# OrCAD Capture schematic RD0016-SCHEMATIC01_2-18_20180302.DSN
size A3
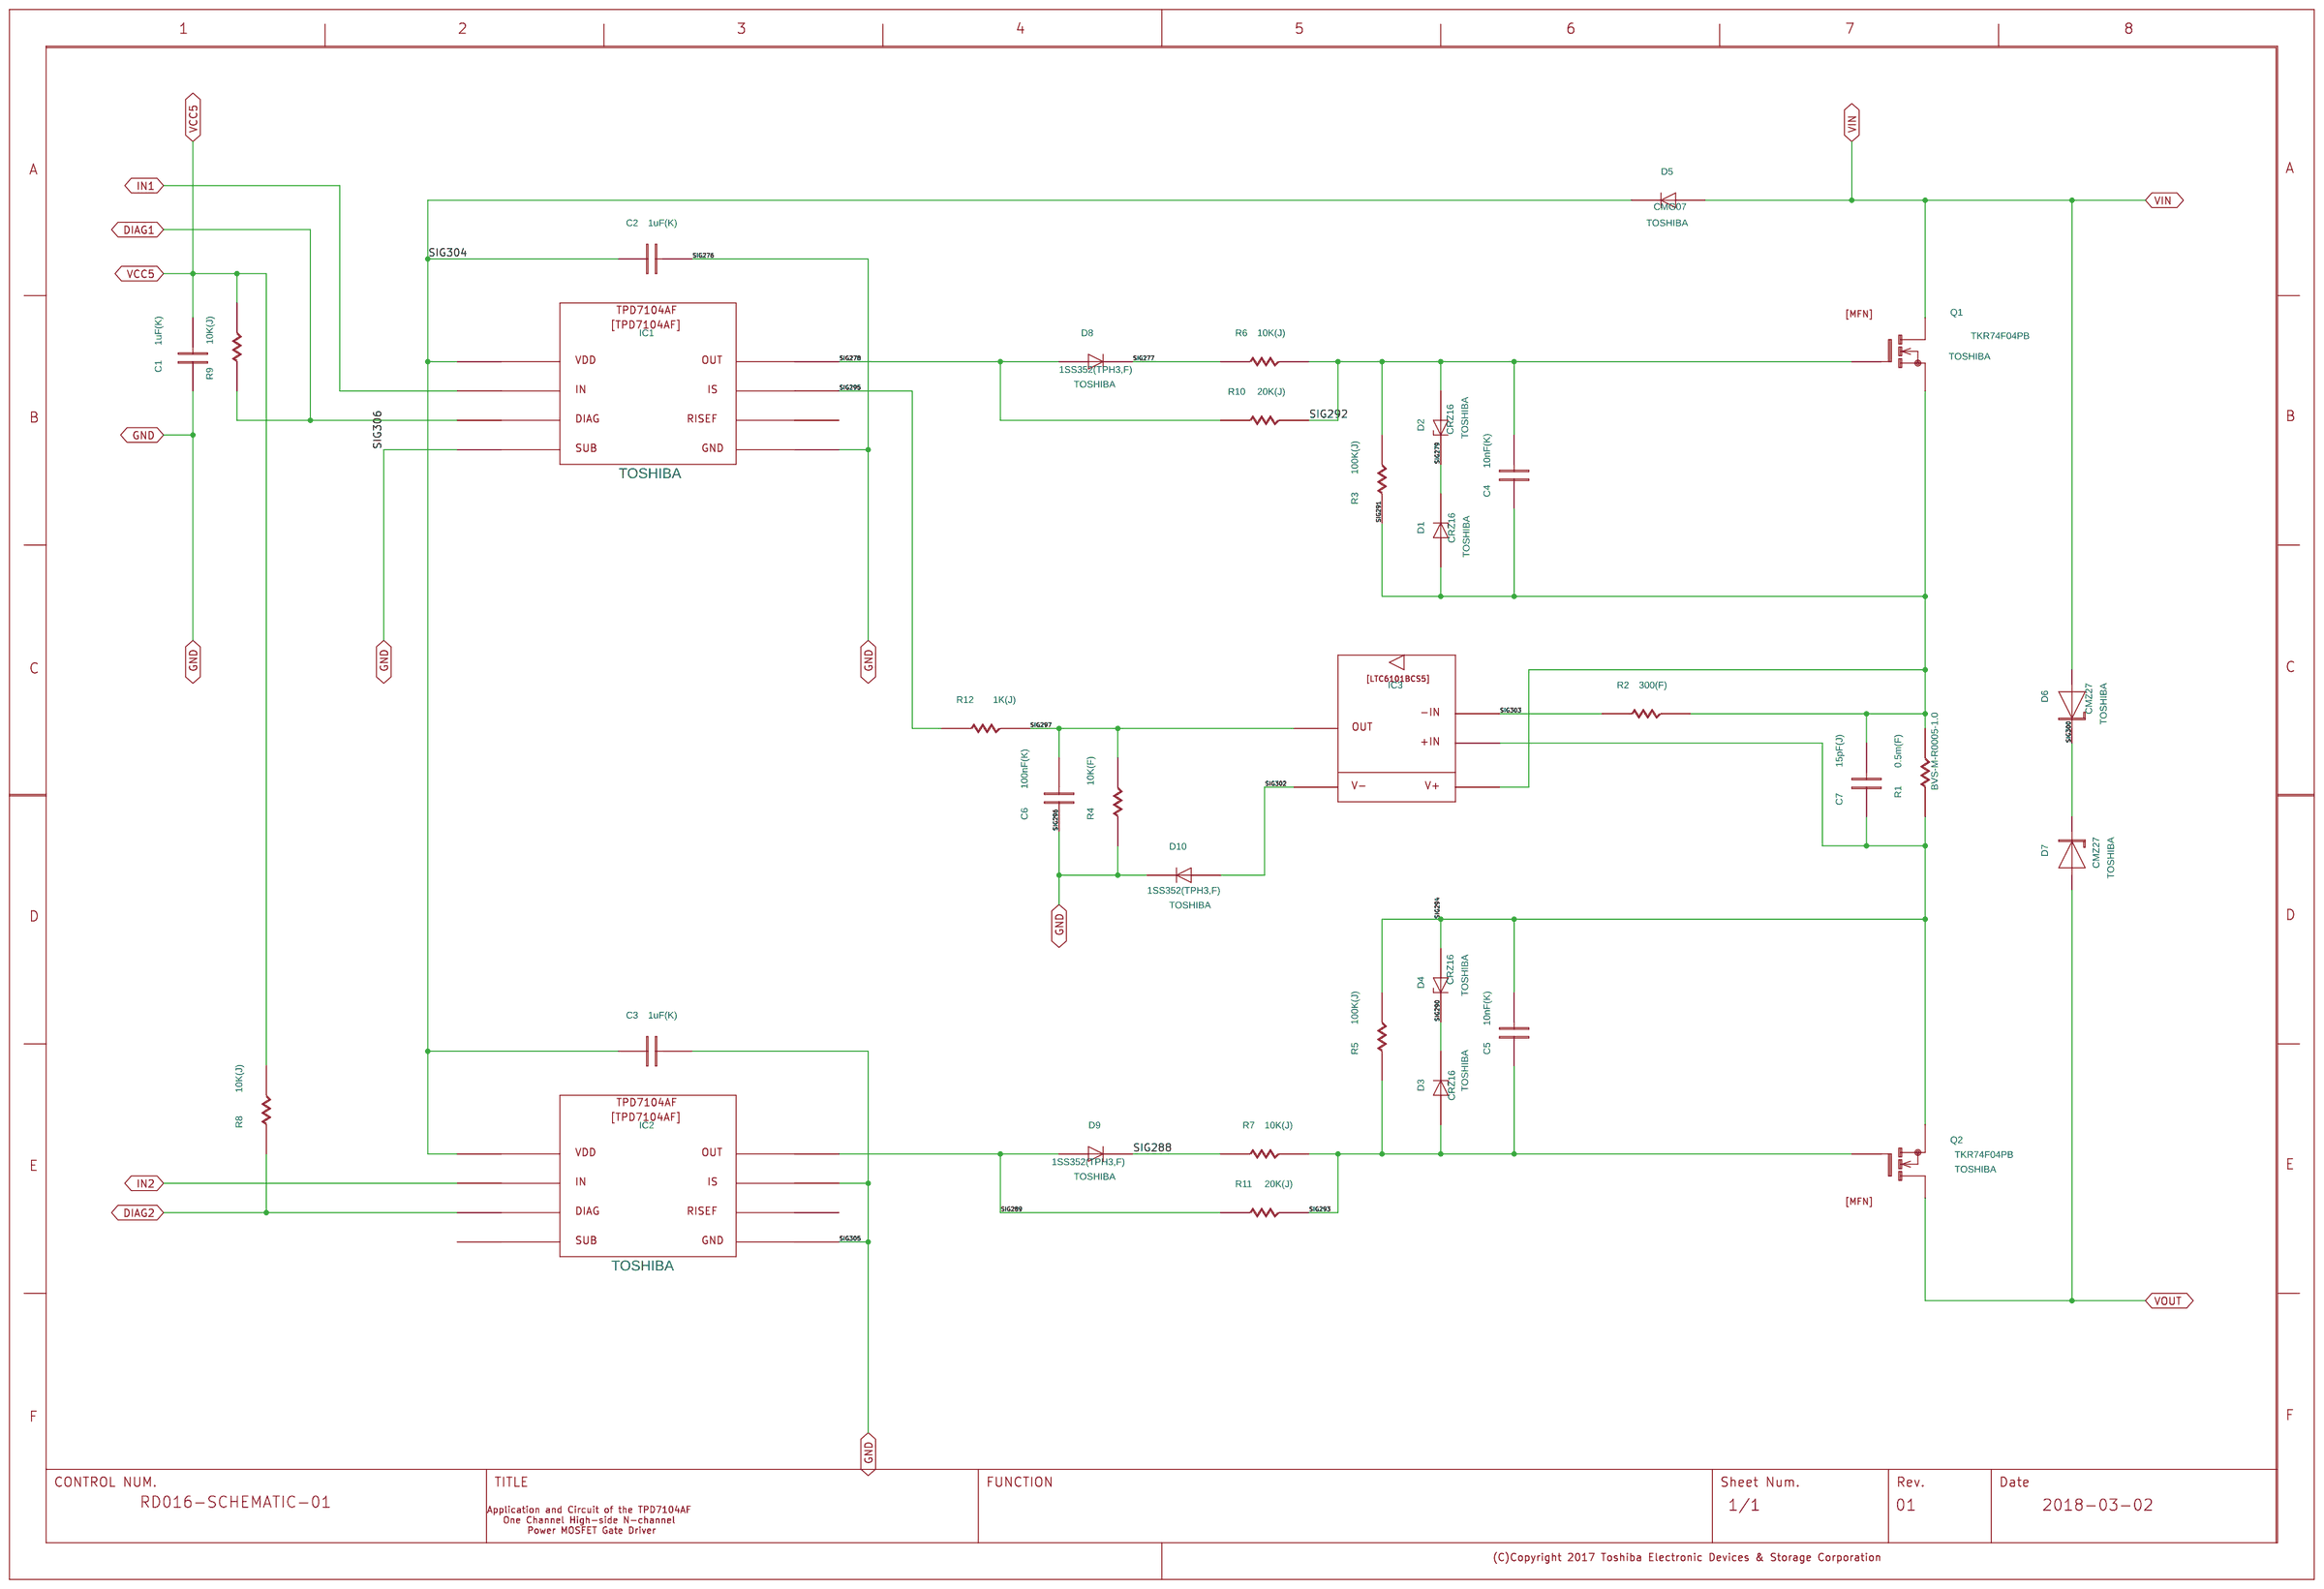
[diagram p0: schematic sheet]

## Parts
C1  C
C2  C
C3  C
C4  C
C5  C
C6  C
C7  C
D1  ZD
D2  ZD
D3  ZD
D4  ZD
D5  D
D6  HM-UDZS10B
D7  HM-UDZS10B
D8  D
D9  D
D10  D
IC1  S-TPD7104AF
IC2  S-TPD7104AF
IC3  S-LTC6101BCS5
Q1  MFN
Q2  MFN
R1  R
R2  R
R3  R
R4  R
R5  R
R6  R
R7  R
R8  R
R9  R
R10  R
R11  R
R12  R
U?#1  WAKU_DEF100

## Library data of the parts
C1-C3 = C: COMP: PRT_15; COMPONENTTYPE: 4; GCOUNT: 1; MAXGCOUNT: 1; SIZECODESMD: 1608; VAL1: 1uF(K); VAL2: 25V
C4 C5 = C: COMP: PRT_16; COMPONENTTYPE: 4; GCOUNT: 1; MAXGCOUNT: 1; SIZECODESMD: 1608; VAL1: 10nF(K); VAL2: 50V
C6 = C: COMP: PRT_17; COMPONENTTYPE: 4; GCOUNT: 1; MAXGCOUNT: 1; SIZECODESMD: 1608; VAL1: 100nF(K); VAL2: 50V
C7 = C: COMP: PRT_18; COMPONENTTYPE: 4; GCOUNT: 1; MAXGCOUNT: 1; SIZECODESMD: 1608; VAL1: 15pF(J); VAL2: 50V
D1-D4 = ZD: COMP: PRT_4; COMPONENTTYPE: 4; GCOUNT: 1; MAXGCOUNT: 1; OUMEPARTTYPE: D; USERCOMPTEXT3: TOSHIBA; VAL1: CRZ16
D5 = D: COMP: PRT_5; COMPONENTTYPE: 4; USERCOMPTEXT3: TOSHIBA; VAL1: CMG07
D6 D7 = HM-UDZS10B: COMP: PRT_6; COMPONENTTYPE: 4; USERCOMPTEXT3: TOSHIBA; VAL1: CMZ27
D8-D10 = D: COMP: PRT_7; COMPONENTTYPE: 4; GCOUNT: 1; MAXGCOUNT: 1; USERCOMPTEXT3: TOSHIBA; VAL1: 1SS352(TPH3,F)
IC1 IC2 = S-TPD7104AF: COMP: PRT_1; COMPONENTTYPE: 4; USERCOMPTEXT3: TOSHIBA
IC3 = S-LTC6101BCS5: COMP: PRT_2; COMPONENTTYPE: 4; USERCOMPTEXT3: ADI
Q1 Q2 = MFN: COMP: PRT_3; COMPONENTTYPE: 4; USERCOMPTEXT3: TOSHIBA; VAL1: TKR74F04PB
R1 = R: ADSCNVFLAG: ON; ADSMODELNAME: s_SRP2R100J; CDMASTERCADCELG: DR828R; COMP: PRT_8; COMPONENTTYPE: 4; FNLEADFREETHET1GT2GMCTH1: N_N_N; GCOUNT: 1; MAXGCOUNT: 1; MOUNTINGFORMSMD: SMD; NOMINALRESISTAN: 100m; OUMECLASSIFICATION: \ÊÀpÅèïRí; OUMEMAKER: SEF ƒZƒCƒfƒ“ƒeƒNƒm; OUMEMAKERKATAMEI: SRP2R100J; POWERRATING: 2; QUADMODEL: RES_100M; RESISTANCETOLER: J; SIZECODESMD: OTH; VAL1: 0.5m(F); VAL2: 5W; VAL3: BVS-M-R0005-1.0
R2 = R: COMP: PRT_9; COMPONENTTYPE: 4; GCOUNT: 1; MAXGCOUNT: 1; SIZECODESMD: 1608; VAL1: 300(F); VAL2: 63mW
R3 R5 = R: COMP: PRT_10; COMPONENTTYPE: 4; GCOUNT: 1; MAXGCOUNT: 1; SIZECODESMD: 1608; VAL1: 100K(J); VAL2: 63mW
R4 = R: COMP: PRT_11; COMPONENTTYPE: 4; GCOUNT: 1; MAXGCOUNT: 1; SIZECODESMD: 1608; VAL1: 10K(F); VAL2: 63mW
R6-R9 = R: COMP: PRT_12; COMPONENTTYPE: 4; GCOUNT: 1; MAXGCOUNT: 1; SIZECODESMD: 1608; VAL1: 10K(J); VAL2: 63mW
R10 R11 = R: COMP: PRT_13; COMPONENTTYPE: 4; GCOUNT: 1; MAXGCOUNT: 1; SIZECODESMD: 1608; VAL1: 20K(J); VAL2: 63mW
R12 = R: COMP: PRT_14; COMPONENTTYPE: 4; GCOUNT: 1; MAXGCOUNT: 1; SIZECODESMD: 1608; VAL1: 1K(J); VAL2: 63mW
U?#1 = WAKU_DEF100: COMPONENTTYPE: 2; DATE: 2018-03-02; DRAWINGNUMBER: RD016-SCHEMATIC-01; FUNCTION: POWER block; REVISION: 01; SHEETNUMBER: 1/1; TITLE: Application and Circuit of the TPD7104AF / One Channel High-side N-channel / Power MOSFET Gate Driver; UPDATEDATE: 2018/03/02; UPDATETIME: 19:53:39; UPDATEUSER: f1043010

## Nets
GND: C1.1 C2.2 C3.2 C6.1 D10.C IC1.4 IC1.5 IC2.2 IC2.5 R4.1
VCC5: C1.2 R8.2 R9.2
VIN: D5.A D6.A Q1.D
DIAG1: IC1.7 R9.1
DIAG2: IC2.7 R8.1
IN1: IC1.6
IN2: IC2.6
SIG277: D8.C R6.1
SIG278: D8.A IC1.3 R10.1
SIG279: D1.C D2.C
SIG288: D9.C R7.1
SIG289: D9.A IC2.3 R11.1
SIG290: D3.C D4.C
SIG291: C4.1 C7.2 D1.A IC3.5 Q1.S R1.2 R2.2 R3.1
SIG292: C4.2 D2.A Q1.G R3.2 R6.2 R10.2
SIG293: C5.1 D3.A Q2.G R5.1 R7.2 R11.2
SIG294: C5.2 C7.1 D4.A IC3.4 Q2.S R1.1 R5.2
SIG295: IC1.2 R12.1
SIG297: C6.2 IC3.1 R4.2 R12.2
SIG300: D6.C D7.C
SIG302: D10.A IC3.2
SIG303: IC3.3 R2.1
SIG304: C2.1 C3.1 D5.C IC1.1 IC2.1
VOUT: D7.A Q2.D

Not connected (* = marked no-connect by the designer): IC1 8; IC2 4 8
